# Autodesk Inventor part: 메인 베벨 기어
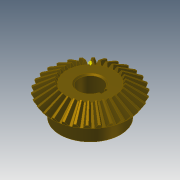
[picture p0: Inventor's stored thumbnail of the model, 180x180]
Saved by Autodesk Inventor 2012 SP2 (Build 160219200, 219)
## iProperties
Created: 2014-10
Part Number: 메인 베벨 기어
Material: Steel, Mild
Document SubType Name: Modeling
Designer: KYOUNG IL JANG
Categories: <?xml version="1.0" encoding="UTF-16"?> <MemberInstance><Categories><FamilyTemplate><FamilyTemplateParameter ValueType="xs:double" Id="1" ObjectReferenceKey="da
Mass: 269.583 g
Surface Area: 108.837 cm^2
Volume: 34.2981 cm^3
Density: 7.86 g/cm^3
CustomPartVersion: 1
Company: 한국ATC센터
Author: KYOUNG IL JANG
Revision Number: 1
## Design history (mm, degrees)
node "맨 위 점"
node "메쉬 평면2"
sketch "톱니 본체 스케치"
  geometry: L1 (0, 0)-(28.669, -21.997); L2 (28.669, -21.997)-(31.109, -18.336); L3 (31.109, -18.336)-(0, 0); L4 (30, -20)-(0, 0); L5 (17.219, -13.212)-(18.685, -11.013); L6 (28.669, -21.997)-(17.219, -13.212); L7 (31.109, -18.336)-(18.685, -11.013); L8 (0, -39.387)-(0, 6.564) reference; L9 (0, -20)-(31.109, -20)
  constraints: 16 end point, 4 point on line, 3 perpendicular, 2 collinear, 1 horizontal alignment, 1 vertical alignment
  dimensions: "d0" = 60 diameter of L4.start L8 (= da_de); "d1" = 57.33744 diameter of L1.end L8 (= da_dfe); "d2" = 62.2188 diameter of L2.end L8 (= da_dae); "d3" = 14.4 distance between parallel lines of L2 L5 (= da_b); "d4" = 18.3359 vertical distance of L2.end L1.start (= da_ve)
revolve "톱니 본체" sketch "톱니 본체 스케치" stored, may be unused: angle "d5" = 90 deg
node "시작점"
node "톱니 평면"
sketch "시작 스케치"
  geometry: L1 (0, -23.505)-(0, 10.645) reference; L2 (-0.709, -2.928)-(0.709, -2.928); A1 r 19.188 centre (-19.457, -7.014) between (-0.709, -2.928) and (-3.232, 3.229); A2 r 19.188 centre (19.457, -7.014) between (3.232, 3.229) and (0.709, -2.928); A3 r 57.403 centre (0, -54.083) between (3.232, 3.229) and (-3.232, 3.229); 1 further point
  constraints: 6 point on circle, 3 centre point, 3 symmetric about line, 2 end point, 1 coincident, 1 perpendicular, 1 other
  dimensions: "d7" = 19.18795 radius of A1 (= fd_rr); "d8" = 19.45712 horizontal distance of point (0, -54.083) A1.centre (= fd_x); "d9" = 47.06905 vertical distance of point (0, -54.083) A1.centre (= fd_y); "d57" = 57.40327 radius of A3 (= 0.5 x fd_dva + 0.3 x da_he); "d58" = 51.15527 distance from line of A3.centre L2 (= 0.5 x fd_dva - 1.12 x da_he)
node "끝점"
  node "끝 평면"
sketch "3D 스케치 오른쪽"
  node "Helical Curve Right" dims "d65" = 229.90621 (computed from da_dm, da_delta, da_beta), "d66" = 31.5, "d67" = 60 (= da_de), "d68" = -9.82794 (= -da_delta), "d69" = 8.10972 (computed from fd_loft, da_delta)
node "끝 평면 오른쪽"
sketch "끝 스케치 오른쪽"
  geometry: L1 (0, -41.54)-(0, 13.178) reference; L2 (-0.422, -1.69)-(0.422, -1.69); A1 r 11.427 centre (-11.587, -4.123) between (-0.422, -1.69) and (-1.925, 1.977); A2 r 11.427 centre (11.587, -4.123) between (1.925, 1.977) and (0.422, -1.69); A3 r 34.184 centre (0, -32.153) between (1.925, 1.977) and (-1.925, 1.977); 1 further point
  constraints: 6 point on circle, 3 centre point, 3 symmetric about line, 2 end point, 1 coincident, 1 perpendicular, 1 other
  dimensions: "d70" = 11.58699 horizontal distance of A3.centre A1.centre (computed from fd_x, fd_ratio); "d71" = 28.03028 vertical distance of point (0, -32.153) A1.centre (computed from fd_y, fd_ratio); "d72" = 11.4267 radius of A1 (computed from fd_rr, fd_ratio); "d73" = 30.46369 distance from line of point (0, -32.153) L2 (computed from d58, fd_ratio); "d74" = 34.18446 radius of A3 (computed from d57, fd_ratio)
feature "로프트 오른쪽" sketch "끝 스케치 오른쪽" dims "d75" = 0, "d77" = 0, "d79" = 0, "d80" = 90 deg, "d85" = 20, "d92" = 90 deg, "d93" = 90 deg, "da_teethtype" = 0 [user parameter]
sketch "3D 스케치 왼쪽"
  node "Helical Curve Left" dims "d26" = 229.90621 (computed from da_dm, da_delta, da_beta), "d27" = 8.10972 (computed from fd_loft, da_delta), "d28" = 60 (= da_de), "d29" = -9.82794 (= -da_delta)
node "끝 평면 왼쪽"
sketch "끝 스케치 왼쪽" dims "d56" = 10.3728 (derived)
  geometry: L1 (0, -43.753)-(0, 15.405) reference; L2 (-0.422, -1.678)-(0.422, -1.678); A1 r 11.427 centre (-11.587, -4.111) between (-0.422, -1.678) and (-1.925, 1.988); A2 r 11.427 centre (11.587, -4.111) between (1.925, 1.988) and (0.422, -1.678); A3 r 34.184 centre (0, -32.142) between (1.925, 1.988) and (-1.925, 1.988); 2 further points; 1 other entity
  constraints: 6 point on circle, 3 centre point, 3 symmetric about line, 2 end point, 1 coincident, 2 other
  dimensions: "d30" = 11.4267 radius of A1 (computed from fd_rr, fd_ratio); "d31" = 11.58699 horizontal distance of point (0, -32.142) A1.centre (computed from fd_x, fd_ratio); "d32" = 28.03028 vertical distance of A1.centre point (0, -32.142) (computed from fd_y, fd_ratio); "d61" = 34.18446 radius of A3 (computed from d57, fd_ratio); "d62" = 30.46369 distance from line of point (0, -32.142) L2 (computed from d58, fd_ratio)
feature "로프트 왼쪽" sketch "끝 스케치 왼쪽" dims "d35" = 0, "d37" = 0, "d39" = 0, "d40" = 90 deg, "d84" = 10, "d90" = 90 deg, "d91" = 90 deg, "da_teethtype" = 0 [user parameter]
sketch "본체 스케치"
  geometry: L1 (0, -35.038)-(0, -19.531) reference; L2 (28.669, -21.997)-(17.219, -13.212) reference; L3 (17.219, -13.212)-(0, -13.212); L4 (28.669, -21.997)-(0, -21.997)
  constraints: 4 end point, 2 perpendicular, 2 point on line
revolve "본체 고정" sketch "본체 스케치" stored, may be unused: angle "d46" = 90 deg
sketch "Sketch6"
  geometry: L1 (30, -20)-(0, 0) reference; L2 (0, -37.8)-(0, 6.3) reference
feature "피치 지름" sketch "Sketch6" dims angle "d47" = 90 deg
sketch "스케치8"
  geometry: C1 r 22.5 at (0, 0); 1 further point
  constraints: 1 centre point, 1 coincident
  dimensions: "d94" = 45 diameter of C1
extrude "돌출1" join sketch "스케치8" distance "d95" = 13; taper "d96" = 0 deg
sketch "스케치9"
  geometry: 1 further point
hole "구멍1" sketch "스케치9" at (0, 0) diameter "d97" = 17; stored, may be unused: countersink angle "d101" = 90 deg, drill point angle "d103" = 118 deg; dims "d98" = 6, "d99" = 4, "d100" = 2, "d102" = 8
sketch "스케치10"
  geometry: L1 (8.124, 2.5)-(10.8, 2.5); L2 (10.8, 2.5)-(10.8, -2.5); L3 (10.8, -2.5)-(8.124, -2.5); A1 r 8.5 centre (0, 0) between (8.124, 2.5) and (8.124, -2.5) reference; 1 further point
  constraints: 6 end point, 2 parallel, 2 point on circle, 1 horizontal, 1 perpendicular
  dimensions: "d104" = 5 distance of L1.end L2.end; "d112" = 19.3 dimension on A1 L2
extrude "돌출2" cut sketch "스케치10" stored distance "d106" = 10; taper "d107" = 0 deg
chamfer "모따기1" distance "d108" = 1; stored, may be unused: second distance "d109" = 2, angle "d110" = 45 deg
fillet "모깎기1" dims "d111" = 2
body "Solid1"
feature "로프트" dims "d17" = 0, "d18" = 90 deg, "d19" = 0, "d20" = 90 deg, "d89" = 0, "da_teethtype" = 0 [user parameter]
pattern_circular "원형 패턴" dims angle "d22" = 360 deg, "d88" = 0, "da_teethtype" = 0 [user parameter]
pattern_circular "원형 패턴 오른쪽" dims angle "d82" = 360 deg, "da_teethtype" = 0 [user parameter]
pattern_circular "원형 패턴 왼쪽" dims angle "d42" = 360 deg, "da_teethtype" = 0 [user parameter]
sketch "끝 스케치"
  geometry: L1 (0, -15.359)-(0, 6.983) reference; L2 (-0.422, -1.69)-(0.422, -1.69); A1 r 11.427 centre (-11.587, -4.123) between (-0.422, -1.69) and (-1.925, 1.977); A2 r 11.427 centre (11.587, -4.123) between (1.925, 1.977) and (0.422, -1.69); A3 r 34.184 centre (0, -32.153) between (1.925, 1.977) and (-1.925, 1.977); 1 further point
  constraints: 6 point on circle, 3 centre point, 3 symmetric about line, 2 end point, 1 coincident, 1 other
  dimensions: "d12" = 11.4267 radius of A1 (computed from fd_rr, fd_ratio); "d15" = 11.58699 horizontal distance of A1.centre point (0, -32.153) (computed from fd_x, fd_ratio); "d16" = 28.03028 vertical distance of A1.centre point (0, -32.153) (computed from fd_y, fd_ratio); "d59" = 34.18446 radius of A3 (computed from d57, fd_ratio); "d60" = 30.46369 distance from line of A3.centre L2 (computed from d58, fd_ratio)
body "Srf1"
other parameters: "da_b" = 14.4 [user parameter; used in 2 equation terms], "da_de" = 60 [user parameter; used in 4 equation terms], "da_dae" = 62.2188 [user parameter; used in 2 equation terms], "da_dfe" = 57.33744 [user parameter; used in 1 equation term], "da_le" = 36.05551 [user parameter; used in 1 equation term], "da_omega" = 90 deg [user parameter; used in 1 equation term], "da_beta" = 0 [user parameter; used in 2 equation terms], "da_delta" = 9.82794 [user parameter; used in 8 equation terms], "da_alpha" = 20 deg [user parameter; used in 2 equation terms], "da_he" = 4.4 [user parameter; used in 4 equation terms], "da_ve" = 18.3359 [user parameter; used in 1 equation term], "fd_dv" = 108.16654 (computed from da_de, da_delta) [user parameter; used in 1 equation term], "fd_dva" = 112.16654 (computed from da_dae, da_delta) [user parameter; used in 3 equation terms], "fd_dvb" = 101.6433 (computed from fd_dv, da_alpha) [user parameter; used in 2 equation terms], "da_zv" = 540.83269 [user parameter; used in 1 equation term], "fd_loft" = 14.62 (= da_b + 0.05 x da_he) [user parameter; used in 4 equation terms], "fd_ratio" = 5.95514 (computed from da_le, fd_loft) [user parameter; used in 15 equation terms], "fd_rr" = 19.18795 (computed from fd_dd, fd_dvb) [user parameter; used in 6 equation terms], "fd_angle" = 0.29367 (computed from da_zv) [user parameter; used in 4 equation terms], "fd_x1" = 1.58802 (computed from da_dvw, fd_angle) [user parameter; used in 1 equation term], "fd_y1" = 54.05995 (computed from da_dvw, fd_angle) [user parameter; used in 1 equation term], "fd_x2" = 17.8691 (computed from fd_rr, fd_angle2, fd_angle) [user parameter; used in 1 equation term], "fd_y2" = 6.9909 (computed from fd_rr, fd_angle2, fd_angle) [user parameter; used in 1 equation term], "fd_x" = 19.45712 (= fd_x1 + fd_x2) [user parameter; used in 4 equation terms], "fd_y" = 47.06905 (= fd_y1 - fd_y2) [user parameter; used in 4 equation terms], "fd_angle2" = 3.43555 (computed from fd_dvb, fd_dd, da_alpha) [user parameter; used in 2 equation terms], "fd_dd" = 108.64654 (= fd_dva - 0.8 x da_he) [user parameter; used in 2 equation terms], "da_dvw" = 108.16654 [user parameter; used in 2 equation terms], "d11" = 14.62 (= fd_loft), "da_dm" = 48.01848 [user parameter; used in 2 equation terms], "da_x" = 0 [user parameter], "da_m" = 2 [user parameter], "d48" = 0, "d49" = 0, "d50" = 90 deg (= da_omega), "d51" = 6 deg (computed from da_z), "d52" = 0, "d53" = 0, "d54" = 0
